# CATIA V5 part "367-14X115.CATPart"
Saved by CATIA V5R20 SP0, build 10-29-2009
Part number: 367-14X115
Definition: NONE
Nomenclature: 367-14X115
Source: Unknown
Description: 367-14X115
Bounding box of the stored display mesh (mm): x 0 to 115, y -14 to 14, z -14 to 14
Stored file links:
  C:\Users\Utente\Desktop\IO LAVORO\3D X SITO CF\X SITO\PLASTICA\3D files 367\367-14X115.CATPart
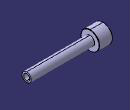
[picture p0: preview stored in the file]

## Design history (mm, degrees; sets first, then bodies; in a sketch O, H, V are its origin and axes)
Body1 "367-14X115" (main body)
  Solid1: solid without history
